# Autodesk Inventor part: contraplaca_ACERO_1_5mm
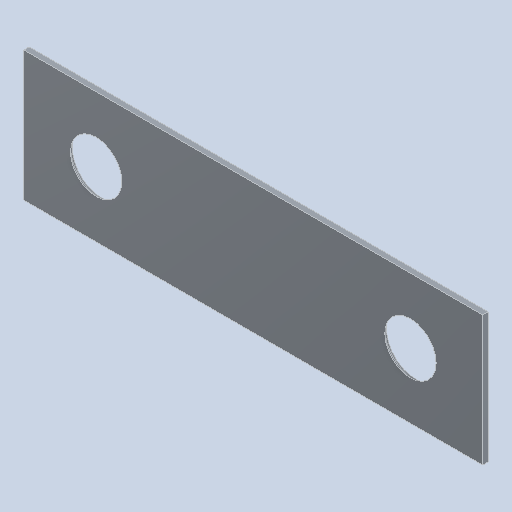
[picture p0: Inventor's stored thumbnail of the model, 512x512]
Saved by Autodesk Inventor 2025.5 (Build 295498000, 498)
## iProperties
Created: 2026-10
Part Number: contraplaca_ACERO_1_5mm
Material: Genérico
Document SubType Name: Modeling
Designer: Luis M
Density: 1 g/cm^3
Appearance: Valor por defecto
Author: Luis M
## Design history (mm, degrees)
feature "Base1"
node "Sólido1"
